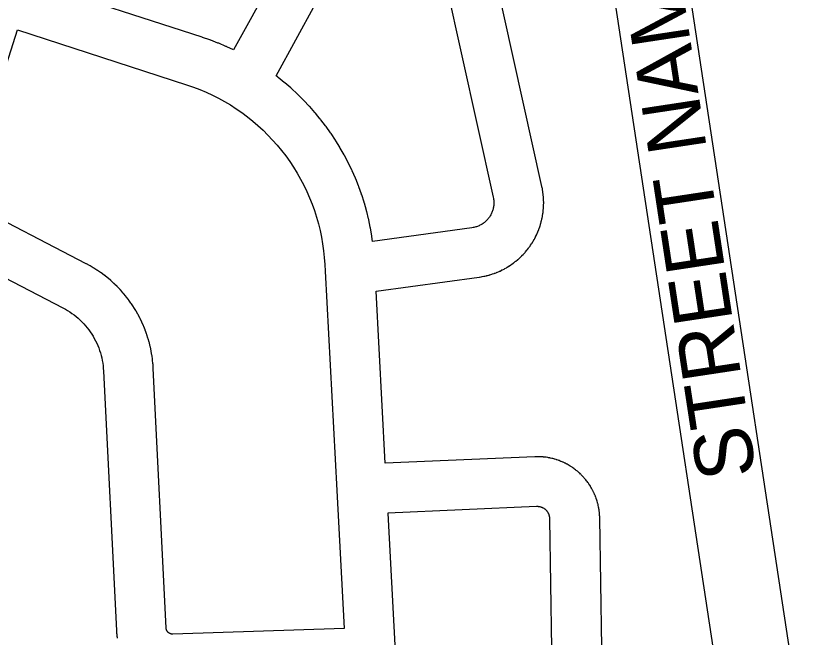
# Model space of a CAD drawing. Extents: x 599744 to 600217, y 4827560 to 4828065.
# Drawn here: x 600025.18 to 600034.69, y 4827982.73 to 4827990.19 of the extents above; entities that cross this region are included whole.
import ezdxf

# ---------------------------------------------------------------- set-up
doc = ezdxf.new("R2010")
doc.units = 0
doc.layers.add('G-ANNO-KEYP', color=7, linetype='Continuous')

msp = doc.modelspace()

# ---------------------------------------------------------------- linework, layer by layer
at = {"layer": 'G-ANNO-KEYP'}
for points in [[(600045.3769, 4827993.0091), (600045.1004, 4827993.1177), (600044.8205, 4827993.2166), (600044.5375, 4827993.3056), (600044.2512, 4827993.3848), (600043.9627, 4827993.454), (600043.6714, 4827993.5132), (600043.3787, 4827993.5622), (600043.0846, 4827993.601), (600042.7889, 4827993.6296), (600042.4925, 4827993.6479), (600042.1956, 4827993.6559), (600041.8988, 4827993.6536), (600041.6025, 4827993.641), (600041.3019, 4827993.6177), (600032.9149, 4827992.8222), (600035.1977, 4827977.7698)], [(600034.4366, 4827976.79), (600032.0181, 4827992.7371)], [(600028.2575, 4827990.6235), (600027.7934, 4827989.782), (600027.7125, 4827989.8195), (600027.7094, 4827989.82), (600027.7031, 4827989.8236), (600027.6175, 4827989.8598), (600027.6139, 4827989.8603), (600027.6079, 4827989.8637), (600027.5212, 4827989.8968), (600027.5171, 4827989.8973), (600027.5115, 4827989.9003), (600027.4237, 4827989.9305), (600027.4215, 4827989.9308), (600027.4188, 4827989.9322), (600025.3816, 4827990.5932)], [(600031.5133, 4827987.8534), (600031.5145, 4827987.8563), (600031.5163, 4827987.8778), (600031.5162, 4827987.8862), (600031.5171, 4827987.8886), (600031.5182, 4827987.9101), (600031.5178, 4827987.919), (600031.5185, 4827987.9209), (600031.5188, 4827987.9424), (600031.5183, 4827987.9516), (600031.5188, 4827987.953), (600031.5184, 4827987.9746), (600031.5176, 4827987.9845), (600031.5179, 4827987.9854), (600031.5167, 4827988.0069), (600031.5158, 4827988.0172), (600031.5159, 4827988.0176), (600031.5139, 4827988.039), (600031.5129, 4827988.0483), (600031.5127, 4827988.0498), (600031.5101, 4827988.0697), (600031.5101, 4827988.0697), (600031.5101, 4827988.07), (600031.5099, 4827988.0712), (600031.5099, 4827988.0713), (600031.5084, 4827988.0817), (600031.5049, 4827988.103), (600031.5046, 4827988.1035), (600031.5029, 4827988.1137), (600031.4986, 4827988.1348), (600031.4983, 4827988.1353), (600031.4975, 4827988.14), (600030.9304, 4827990.6931)], [(600030.3465, 4827990.5606), (600030.9123, 4827988.0128), (600030.915, 4827987.9995), (600030.9168, 4827987.9888), (600030.9182, 4827987.9782), (600030.9192, 4827987.9677), (600030.9198, 4827987.9567), (600030.92, 4827987.9459), (600030.9199, 4827987.9349), (600030.9193, 4827987.9243), (600030.9184, 4827987.9137), (600030.917, 4827987.9025), (600030.9154, 4827987.8924), (600030.9133, 4827987.8816), (600030.9108, 4827987.871), (600030.908, 4827987.8607), (600030.9048, 4827987.8504), (600030.9012, 4827987.8404), (600030.8972, 4827987.83), (600030.8929, 4827987.8203), (600030.8882, 4827987.8105), (600030.8832, 4827987.8009), (600030.8778, 4827987.7914), (600030.8723, 4827987.7825), (600030.8662, 4827987.7734), (600030.86, 4827987.7647), (600030.8532, 4827987.7561), (600030.8463, 4827987.7478), (600030.8391, 4827987.7398), (600030.8317, 4827987.7322)], [(600029.1706, 4827988.4308), (600029.1275, 4827988.5131), (600029.1243, 4827988.5169), (600029.1226, 4827988.5221), (600029.0766, 4827988.6029), (600029.073, 4827988.607), (600029.0714, 4827988.6117), (600029.0227, 4827988.6908), (600029.0187, 4827988.6952), (600029.0171, 4827988.6995), (600028.9657, 4827988.7769), (600028.9614, 4827988.7816), (600028.9599, 4827988.7854), (600028.9059, 4827988.8609), (600028.9011, 4827988.8659), (600028.8998, 4827988.8692), (600028.8432, 4827988.9428), (600028.838, 4827988.9481), (600028.8368, 4827988.9509), (600028.7777, 4827989.0226), (600028.7721, 4827989.0281), (600028.771, 4827989.0304), (600028.7095, 4827989.1), (600028.7034, 4827989.1057), (600028.7025, 4827989.1076), (600028.6387, 4827989.1751), (600028.6322, 4827989.181), (600028.6315, 4827989.1824), (600028.5653, 4827989.2476), (600028.5584, 4827989.2537), (600028.5578, 4827989.2547), (600028.4895, 4827989.3176), (600028.4821, 4827989.3239), (600028.4818, 4827989.3244), (600028.4113, 4827989.3849), (600028.4035, 4827989.3914), (600028.4034, 4827989.3915), (600028.3309, 4827989.4496), (600028.3277, 4827989.4521), (600028.3227, 4827989.4559), (600028.3047, 4827989.4693), (600028.7806, 4827990.3321)], [(600024.5694, 4827987.995), (600024.5686, 4827987.9979), (600024.5679, 4827988.0003), (600024.5674, 4827988.0028), (600024.5669, 4827988.0057), (600024.5665, 4827988.0085), (600024.5662, 4827988.0111), (600024.5661, 4827988.0136), (600024.566, 4827988.0164), (600024.566, 4827988.0192), (600024.5661, 4827988.0222), (600024.5663, 4827988.0245), (600024.5666, 4827988.0273), (600024.5669, 4827988.0299), (600024.5675, 4827988.0329), (600024.568, 4827988.0352), (600024.5687, 4827988.038), (600024.5701, 4827988.0427), (600025.2001, 4827990.0225)], [(600025.2001, 4827990.0225), (600027.2317, 4827989.3633), (600027.3121, 4827989.3357), (600027.3891, 4827989.3063), (600027.4653, 4827989.2741), (600027.5404, 4827989.2392), (600027.6138, 4827989.2021), (600027.6862, 4827989.1623), (600027.7571, 4827989.12), (600027.8269, 4827989.0751), (600027.8943, 4827989.0284), (600027.9606, 4827988.9789), (600028.0253, 4827988.9271), (600028.0878, 4827988.8735), (600028.1487, 4827988.8175), (600028.2073, 4827988.7597), (600028.2643, 4827988.6995), (600028.3188, 4827988.6379), (600028.3715, 4827988.574), (600028.4218, 4827988.5084), (600028.4696, 4827988.4415), (600028.5155, 4827988.3724), (600028.5586, 4827988.3024), (600028.5996, 4827988.2303), (600028.6379, 4827988.1573), (600028.6737, 4827988.0829), (600028.707, 4827988.0073), (600028.7375, 4827987.9308), (600028.7655, 4827987.8529), (600028.7909, 4827987.774), (600028.8133, 4827987.6948), (600028.8331, 4827987.6148), (600028.8502, 4827987.5338), (600028.8644, 4827987.4526), (600028.8759, 4827987.3707), (600028.8845, 4827987.2883), (600028.8904, 4827987.2042), (600028.8945, 4827987.1268), (600028.8945, 4827987.1268), (600029.034, 4827984.4936), (600029.1217, 4827982.8368), (600027.0674, 4827982.7702), (600027.0614, 4827982.7701), (600027.0588, 4827982.7701), (600027.056, 4827982.7703), (600027.0533, 4827982.7706), (600027.0504, 4827982.7709), (600027.0478, 4827982.7714), (600027.0453, 4827982.7719), (600027.0423, 4827982.7726)], [(600030.8317, 4827987.7322), (600030.8238, 4827987.7245), (600030.8157, 4827987.7174), (600030.8075, 4827987.7105), (600030.799, 4827987.7039), (600030.7902, 4827987.6976), (600030.781, 4827987.6915), (600030.7721, 4827987.6861), (600030.7625, 4827987.6806), (600030.7529, 4827987.6757), (600030.7432, 4827987.6711), (600030.7334, 4827987.6669), (600030.7231, 4827987.6629), (600030.7132, 4827987.6594), (600030.7028, 4827987.6562), (600030.6922, 4827987.6534), (600030.6818, 4827987.6509), (600030.671, 4827987.6489), (600030.6578, 4827987.6468), (600029.4649, 4827987.4823), (600029.4568, 4827987.5405), (600029.4567, 4827987.5407), (600029.4551, 4827987.5507), (600029.4391, 4827987.6422), (600029.4388, 4827987.6428), (600029.4372, 4827987.6523), (600029.418, 4827987.7432), (600029.4174, 4827987.7442), (600029.4157, 4827987.7532), (600029.3934, 4827987.8434), (600029.3925, 4827987.8448), (600029.3908, 4827987.8534), (600029.3654, 4827987.9427), (600029.3643, 4827987.9445), (600029.3625, 4827987.9525), (600029.3341, 4827988.041), (600029.3326, 4827988.0431), (600029.3307, 4827988.0508), (600029.2993, 4827988.1382), (600029.2975, 4827988.1407), (600029.2956, 4827988.1477), (600029.2612, 4827988.234), (600029.2591, 4827988.2369), (600029.2572, 4827988.2436), (600029.2198, 4827988.3286), (600029.2173, 4827988.3318), (600029.2155, 4827988.3379), (600029.1752, 4827988.4216), (600029.1724, 4827988.4251), (600029.1706, 4827988.4308)], [(600026.3971, 4827986.9406), (600026.3963, 4827986.942), (600026.3665, 4827986.9711), (600026.3595, 4827986.9773), (600026.359, 4827986.9782), (600026.3282, 4827987.0063), (600026.3206, 4827987.0127), (600026.3203, 4827987.0133), (600026.2885, 4827987.0403), (600026.2806, 4827987.0467), (600026.2805, 4827987.0468), (600026.2478, 4827987.0727), (600026.2459, 4827987.0742), (600026.2395, 4827987.079), (600026.206, 4827987.1038), (600026.2056, 4827987.1039), (600026.1975, 4827987.1098), (600026.1631, 4827987.1333), (600026.1623, 4827987.1335), (600026.1544, 4827987.1391), (600026.1192, 4827987.1614), (600026.1179, 4827987.1617), (600026.1103, 4827987.1668), (600026.0744, 4827987.1879), (600026.0725, 4827987.1883), (600026.0652, 4827987.1931), (600026.0285, 4827987.2129), (600026.0274, 4827987.2131), (600026.024, 4827987.2153), (600024.6093, 4827987.9491)], [(600031.2803, 4827987.335), (600031.2948, 4827987.351), (600031.3015, 4827987.359), (600031.302, 4827987.3593), (600031.3158, 4827987.3758), (600031.3225, 4827987.384), (600031.3357, 4827987.401), (600031.3421, 4827987.4096), (600031.3548, 4827987.4271), (600031.3549, 4827987.4276), (600031.3609, 4827987.4359), (600031.3729, 4827987.4538), (600031.3731, 4827987.4549), (600031.3788, 4827987.463), (600031.3901, 4827987.4813), (600031.3904, 4827987.4828), (600031.3955, 4827987.4904), (600031.4062, 4827987.5092), (600031.4066, 4827987.5112), (600031.4114, 4827987.5187), (600031.4214, 4827987.5378), (600031.4218, 4827987.5403), (600031.4262, 4827987.5474), (600031.4355, 4827987.5668), (600031.436, 4827987.5699), (600031.4399, 4827987.5766), (600031.4485, 4827987.5964), (600031.4491, 4827987.6), (600031.4527, 4827987.6064), (600031.4605, 4827987.6264), (600031.4611, 4827987.6306), (600031.4642, 4827987.6364), (600031.4714, 4827987.6568), (600031.4719, 4827987.6614), (600031.4748, 4827987.6669), (600031.4812, 4827987.6874), (600031.4817, 4827987.6927), (600031.4842, 4827987.6979), (600031.4899, 4827987.7187), (600031.4903, 4827987.7244), (600031.4925, 4827987.7291), (600031.4975, 4827987.7501), (600031.4978, 4827987.7564), (600031.4997, 4827987.7606), (600031.5039, 4827987.7818), (600031.5042, 4827987.7885), (600031.5058, 4827987.7923), (600031.5092, 4827987.8136), (600031.5093, 4827987.8209), (600031.5107, 4827987.8243), (600031.5133, 4827987.8457), (600031.5133, 4827987.8534)], [(600024.331, 4827987.419), (600025.7461, 4827986.6849), (600025.7757, 4827986.6689), (600025.8027, 4827986.6531), (600025.8292, 4827986.6362), (600025.855, 4827986.6186), (600025.8801, 4827986.6001), (600025.9048, 4827986.5806), (600025.9287, 4827986.5603), (600025.9518, 4827986.5392), (600025.9742, 4827986.5173), (600025.9957, 4827986.4948), (600026.0164, 4827986.4715), (600026.0365, 4827986.4473), (600026.0556, 4827986.4225), (600026.074, 4827986.3969), (600026.0913, 4827986.3711), (600026.1077, 4827986.3444), (600026.1232, 4827986.3174), (600026.1378, 4827986.2897), (600026.1514, 4827986.2613), (600026.1641, 4827986.2325), (600026.1756, 4827986.2038), (600026.1862, 4827986.1743), (600026.1958, 4827986.1444), (600026.2043, 4827986.1143), (600026.2117, 4827986.0841), (600026.2181, 4827986.0534), (600026.2235, 4827986.0222), (600026.2278, 4827985.9914), (600026.2309, 4827985.9603), (600026.2332, 4827985.9268), (600026.3882, 4827982.8121), (600026.3886, 4827982.807), (600026.3885, 4827982.8066), (600026.3894, 4827982.7931), (600026.3904, 4827982.7825), (600026.3903, 4827982.7823), (600026.3918, 4827982.7688), (600026.3924, 4827982.763), (600026.393, 4827982.7583), (600026.3949, 4827982.7448), (600026.3951, 4827982.7447), (600026.3967, 4827982.7341), (600026.399, 4827982.7208)], [(600030.8335, 4827987.072), (600030.8427, 4827987.0737), (600030.8635, 4827987.0794), (600030.8652, 4827987.0805), (600030.8737, 4827987.0823), (600030.8943, 4827987.0886), (600030.8964, 4827987.0901), (600030.9045, 4827987.092), (600030.9248, 4827987.099), (600030.9274, 4827987.1009), (600030.9351, 4827987.1028), (600030.9552, 4827987.1106), (600030.9581, 4827987.1128), (600030.9651, 4827987.1147), (600030.9849, 4827987.1232), (600030.9882, 4827987.1257), (600030.9947, 4827987.1276), (600031.0141, 4827987.1368), (600031.0177, 4827987.1397), (600031.0237, 4827987.1416), (600031.0429, 4827987.1515), (600031.0469, 4827987.1548), (600031.0524, 4827987.1567), (600031.0711, 4827987.1673), (600031.0755, 4827987.171), (600031.0804, 4827987.1727), (600031.0988, 4827987.184), (600031.1034, 4827987.1881), (600031.1078, 4827987.1897), (600031.1257, 4827987.2016), (600031.1307, 4827987.2063), (600031.1346, 4827987.2078), (600031.1522, 4827987.2203), (600031.1574, 4827987.2254), (600031.1608, 4827987.2268), (600031.1778, 4827987.2399), (600031.1833, 4827987.2454), (600031.1862, 4827987.2467), (600031.2028, 4827987.2605), (600031.2086, 4827987.2664), (600031.211, 4827987.2675), (600031.2271, 4827987.2819), (600031.233, 4827987.2882), (600031.2349, 4827987.2891), (600031.2504, 4827987.3041), (600031.2567, 4827987.311), (600031.2581, 4827987.3117), (600031.2731, 4827987.3272), (600031.2794, 4827987.3345), (600031.2803, 4827987.335)], [(600031.7279, 4827984.8426), (600031.7241, 4827984.8431), (600031.718, 4827984.8466), (600031.7031, 4827984.8523), (600031.6988, 4827984.8528), (600031.6929, 4827984.856), (600031.6778, 4827984.8611), (600031.6732, 4827984.8616), (600031.668, 4827984.8643), (600031.6527, 4827984.869), (600031.6473, 4827984.8694), (600031.6423, 4827984.8719), (600031.6269, 4827984.876), (600031.621, 4827984.8764), (600031.6164, 4827984.8786), (600031.6008, 4827984.8821), (600031.5946, 4827984.8824), (600031.5906, 4827984.8843), (600031.5748, 4827984.8872), (600031.5681, 4827984.8875), (600031.5644, 4827984.889), (600031.5486, 4827984.8915), (600031.5411, 4827984.8916), (600031.5378, 4827984.8929), (600031.522, 4827984.8948), (600031.5143, 4827984.8948), (600031.5116, 4827984.8958), (600031.4956, 4827984.8971), (600031.4873, 4827984.897), (600031.4849, 4827984.8978), (600031.469, 4827984.8985), (600031.4603, 4827984.8982), (600031.4585, 4827984.8988), (600031.4425, 4827984.899), (600031.4331, 4827984.8985), (600031.4317, 4827984.8989), (600031.4157, 4827984.8985), (600031.411, 4827984.8982), (600031.4105, 4827984.8983), (600029.6163, 4827984.8213), (600029.507, 4827986.8837), (600030.7423, 4827987.054), (600030.7424, 4827987.054), (600030.7477, 4827987.0548), (600030.769, 4827987.0581), (600030.7693, 4827987.0583), (600030.7795, 4827987.0599), (600030.8006, 4827987.064), (600030.8015, 4827987.0646), (600030.8113, 4827987.0663), (600030.8323, 4827987.0711), (600030.8335, 4827987.072)], [(600026.7968, 4827986.2116), (600026.7962, 4827986.2126), (600026.7945, 4827986.2217), (600026.7846, 4827986.2622), (600026.7837, 4827986.2636), (600026.7819, 4827986.2723), (600026.7706, 4827986.3124), (600026.7693, 4827986.3142), (600026.7675, 4827986.3224), (600026.7548, 4827986.3621), (600026.7533, 4827986.3643), (600026.7515, 4827986.3719), (600026.7374, 4827986.4111), (600026.7355, 4827986.4137), (600026.7336, 4827986.4209), (600026.7182, 4827986.4596), (600026.716, 4827986.4625), (600026.7142, 4827986.4692), (600026.6974, 4827986.5074), (600026.6949, 4827986.5106), (600026.693, 4827986.5168), (600026.6749, 4827986.5544), (600026.672, 4827986.558), (600026.6702, 4827986.5637), (600026.6508, 4827986.6006), (600026.6476, 4827986.6045), (600026.6458, 4827986.6097), (600026.6251, 4827986.6459), (600026.6215, 4827986.6501), (600026.6198, 4827986.6549), (600026.5979, 4827986.6903), (600026.5939, 4827986.6948), (600026.5923, 4827986.699), (600026.5692, 4827986.7337), (600026.5647, 4827986.7385), (600026.5632, 4827986.7423), (600026.5389, 4827986.7762), (600026.534, 4827986.7813), (600026.5326, 4827986.7846), (600026.5071, 4827986.8176), (600026.5019, 4827986.8228), (600026.5007, 4827986.8256), (600026.474, 4827986.8577), (600026.4683, 4827986.8633), (600026.4672, 4827986.8656), (600026.4395, 4827986.8968), (600026.4334, 4827986.9025), (600026.4325, 4827986.9044), (600026.4037, 4827986.9346), (600026.3971, 4827986.9406)], [(600027.0423, 4827982.7726), (600027.0404, 4827982.7732), (600027.0371, 4827982.7742), (600027.035, 4827982.775), (600027.0322, 4827982.7761), (600027.0295, 4827982.7773), (600027.0275, 4827982.7783), (600027.0249, 4827982.7796), (600027.0224, 4827982.7811), (600027.0203, 4827982.7824), (600027.0179, 4827982.7841), (600027.0159, 4827982.7855), (600027.0135, 4827982.7874), (600027.0115, 4827982.7892), (600027.0097, 4827982.7909), (600027.0074, 4827982.7931), (600027.0058, 4827982.7948), (600027.004, 4827982.7969), (600027.0023, 4827982.799), (600027.0005, 4827982.8014), (600026.9991, 4827982.8034), (600026.9977, 4827982.8055), (600026.996, 4827982.8083), (600026.9949, 4827982.8104), (600026.9936, 4827982.813), (600026.9924, 4827982.8155), (600026.9914, 4827982.818), (600026.9905, 4827982.8203), (600026.9896, 4827982.8232), (600026.9888, 4827982.8258), (600026.9882, 4827982.8285), (600026.9876, 4827982.8309), (600026.9871, 4827982.8337), (600026.9868, 4827982.8363), (600026.9865, 4827982.8392), (600026.9861, 4827982.8448), (600026.8311, 4827985.9589), (600026.8307, 4827985.9637), (600026.8308, 4827985.9641), (600026.828, 4827986.0057), (600026.8271, 4827986.0157), (600026.8271, 4827986.016), (600026.8229, 4827986.0575), (600026.8222, 4827986.0641), (600026.8217, 4827986.0679), (600026.816, 4827986.1092), (600026.8159, 4827986.1094), (600026.8144, 4827986.1194), (600026.8073, 4827986.1604), (600026.807, 4827986.161), (600026.8053, 4827986.1708), (600026.7968, 4827986.2116)], [(600032.0651, 4827984.5669), (600032.056, 4827984.5801), (600032.0514, 4827984.585), (600032.0499, 4827984.5886), (600032.0404, 4827984.6015), (600032.0352, 4827984.6069), (600032.0338, 4827984.6101), (600032.0239, 4827984.6226), (600032.0183, 4827984.6281), (600032.0172, 4827984.6307), (600032.0068, 4827984.6429), (600032.0008, 4827984.6486), (600031.9998, 4827984.6508), (600031.989, 4827984.6625), (600031.9823, 4827984.6687), (600031.9814, 4827984.6704), (600031.9702, 4827984.6818), (600031.9634, 4827984.6879), (600031.9628, 4827984.6891), (600031.9512, 4827984.7), (600031.9437, 4827984.7065), (600031.9432, 4827984.7072), (600031.9312, 4827984.7178), (600031.9233, 4827984.7244), (600031.9231, 4827984.7247), (600031.9107, 4827984.7348), (600031.9051, 4827984.7393), (600031.9024, 4827984.7414), (600031.8896, 4827984.7511), (600031.8895, 4827984.7511), (600031.8812, 4827984.7573), (600031.8681, 4827984.7665), (600031.8674, 4827984.7667), (600031.8592, 4827984.7726), (600031.8458, 4827984.7813), (600031.8446, 4827984.7816), (600031.8368, 4827984.7869), (600031.8231, 4827984.7952), (600031.8215, 4827984.7956), (600031.814, 4827984.8005), (600031.8, 4827984.8083), (600031.7978, 4827984.8087), (600031.7905, 4827984.8133), (600031.7763, 4827984.8206), (600031.7736, 4827984.8211), (600031.7668, 4827984.8253), (600031.7523, 4827984.832), (600031.7491, 4827984.8325), (600031.7426, 4827984.8363), (600031.7279, 4827984.8426)], [(600032.2152, 4827982.6096), (600032.1919, 4827984.1609), (600032.1916, 4827984.1656), (600032.1918, 4827984.1662), (600032.1913, 4827984.1822), (600032.1905, 4827984.192), (600032.1907, 4827984.1928), (600032.1896, 4827984.2087), (600032.1887, 4827984.219), (600032.1887, 4827984.2193), (600032.1871, 4827984.2352), (600032.1864, 4827984.2412), (600032.1858, 4827984.2459), (600032.1835, 4827984.2617), (600032.1834, 4827984.2619), (600032.1819, 4827984.2719), (600032.1792, 4827984.2877), (600032.1788, 4827984.2883), (600032.1771, 4827984.2983), (600032.1738, 4827984.3139), (600032.1731, 4827984.315), (600032.1713, 4827984.3245), (600032.1674, 4827984.34), (600032.1665, 4827984.3414), (600032.1647, 4827984.3501), (600032.1602, 4827984.3654), (600032.159, 4827984.3673), (600032.1571, 4827984.3755), (600032.1522, 4827984.3907), (600032.1505, 4827984.393), (600032.1486, 4827984.4008), (600032.1431, 4827984.4158), (600032.1411, 4827984.4185), (600032.1392, 4827984.4258), (600032.1332, 4827984.4406), (600032.1309, 4827984.4436), (600032.129, 4827984.4503), (600032.1225, 4827984.4648), (600032.1198, 4827984.4682), (600032.1179, 4827984.4745), (600032.1108, 4827984.4888), (600032.1078, 4827984.4926), (600032.1059, 4827984.4983), (600032.0983, 4827984.5124), (600032.0949, 4827984.5165), (600032.0931, 4827984.5216), (600032.0851, 4827984.5354), (600032.0812, 4827984.5399), (600032.0795, 4827984.5445), (600032.0709, 4827984.558), (600032.0667, 4827984.5627), (600032.0651, 4827984.5669)], [(600031.6164, 4827982.5988), (600031.5932, 4827984.1496), (600031.593, 4827984.1571), (600031.5926, 4827984.1627), (600031.5921, 4827984.1679), (600031.5913, 4827984.1731), (600031.5903, 4827984.1787), (600031.5893, 4827984.1835), (600031.588, 4827984.1887), (600031.5864, 4827984.1941), (600031.5847, 4827984.1994), (600031.583, 4827984.204), (600031.5809, 4827984.2091), (600031.5787, 4827984.214), (600031.5764, 4827984.2186), (600031.5739, 4827984.2234), (600031.571, 4827984.2283), (600031.5684, 4827984.2323), (600031.5652, 4827984.237), (600031.5619, 4827984.2415), (600031.5589, 4827984.2452), (600031.5552, 4827984.2496), (600031.5515, 4827984.2536), (600031.548, 4827984.2571), (600031.5441, 4827984.2609), (600031.5397, 4827984.2647), (600031.5361, 4827984.2677), (600031.5315, 4827984.2711), (600031.5271, 4827984.2743), (600031.5227, 4827984.2771), (600031.518, 4827984.28), (600031.5135, 4827984.2825), (600031.5088, 4827984.2849), (600031.5038, 4827984.2872), (600031.4988, 4827984.2893), (600031.4942, 4827984.2911), (600031.4887, 4827984.293), (600031.4839, 4827984.2944), (600031.4784, 4827984.2959), (600031.4735, 4827984.297), (600031.468, 4827984.298), (600031.4628, 4827984.2988), (600031.4577, 4827984.2994), (600031.4521, 4827984.2999), (600031.4467, 4827984.3001), (600031.4414, 4827984.3002), (600031.434, 4827984.3), (600029.6479, 4827984.2233), (600029.7359, 4827982.5633)]]:
    msp.add_lwpolyline(points, dxfattribs=at)

# ---------------------------------------------------------------- texts
msp.add_text('STREET NAME', height=0.7, rotation=98.62341, dxfattribs=at).set_placement((600034.0721, 4827984.6834))

doc.saveas('drawing.dxf')
